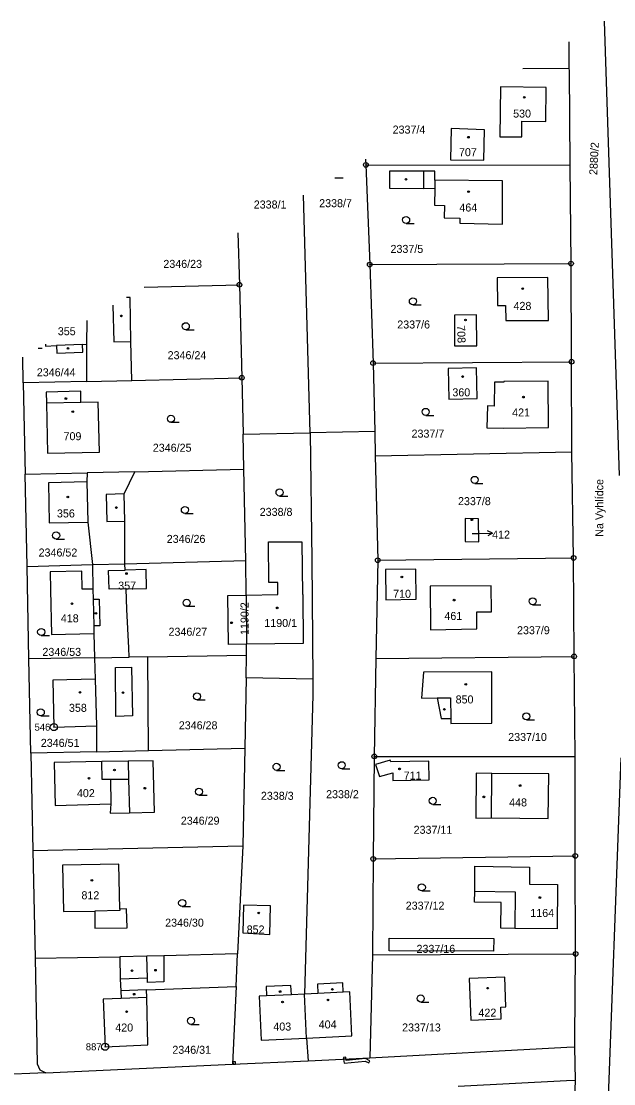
# Model space of a CAD drawing. Extents: x -758836 to -757729, y -1175316 to -1174366.
# Drawn here: x -758715.8 to -758589.9, y -1174936.9 to -1174711.3 of the extents above; entities that cross this region are included whole.
import ezdxf

# ---------------------------------------------------------------- set-up
doc = ezdxf.new("R2010")
doc.units = 0
for name, color, linetype in [('Hranice parcel', 7, 'Continuous'), ('Parcelní čísla', 7, 'Continuous'), ('Pop  PČ popisy', 7, 'Continuous'), ('Vnitřní kresba', 7, 'Continuous'), ('Věcná břemena k části', 7, 'Continuous'), ('Značky bodu BP', 7, 'Continuous'), ('Značky budov', 7, 'Continuous'), ('Značky kultur', 7, 'Continuous')]:
    doc.layers.add(name, color=color, linetype=linetype)

msp = doc.modelspace()

# ---------------------------------------------------------------- linework, layer by layer
at = {"layer": 'Hranice parcel'}
for p, q in [((-758588.72, -1174807.72), (-758591.88, -1174711.27)), ((-758599.38, -1174721.23), (-758599.41, -1174715.61)), ((-758609.26, -1174721.3), (-758599.38, -1174721.23)), ((-758642.64, -1174740.57), (-758642.59, -1174741.77)), ((-758642.59, -1174741.77), (-758641.77, -1174762.95)), ((-758599.02, -1174762.71), (-758599.18, -1174741.82)), ((-758654.45, -1174798.66), (-758655.86, -1174748.2)), ((-758669.76, -1174756.22), (-758669.46, -1174767.22)), ((-758641.77, -1174762.95), (-758599.02, -1174762.71)), ((-758641.77, -1174762.95), (-758641.07, -1174783.86)), ((-758598.91, -1174783.57), (-758599.02, -1174762.71)), ((-758689.66, -1174767.71), (-758669.46, -1174767.22)), ((-758669.46, -1174767.22), (-758668.95, -1174786.98)), ((-758715.38, -1174788.07), (-758715.49, -1174782.63)), ((-758641.07, -1174783.86), (-758640.69, -1174798.38)), ((-758598.81, -1174802.72), (-758598.91, -1174783.57)), ((-758692.34, -1174787.53), (-758668.95, -1174786.98)), ((-758668.95, -1174786.98), (-758668.68, -1174798.94)), ((-758701.96, -1174787.75), (-758715.38, -1174788.07)), ((-758715.38, -1174788.07), (-758714.98, -1174807.46)), ((-758701.96, -1174787.75), (-758692.34, -1174787.53)), ((-758668.68, -1174798.94), (-758654.45, -1174798.66)), ((-758640.69, -1174798.38), (-758654.45, -1174798.66)), ((-758640.69, -1174798.38), (-758640.6, -1174803.53)), ((-758668.51, -1174806.38), (-758668.68, -1174798.94)), ((-758640.6, -1174803.53), (-758598.81, -1174802.72)), ((-758598.48, -1174825.23), (-758598.81, -1174802.72)), ((-758640.6, -1174803.53), (-758640.07, -1174825.71)), ((-758714.98, -1174807.46), (-758701.78, -1174807.15)), ((-758714.57, -1174827.05), (-758714.98, -1174807.46)), ((-758691.67, -1174806.92), (-758701.78, -1174807.15)), ((-758691.67, -1174806.92), (-758668.51, -1174806.38)), ((-758668.07, -1174825.76), (-758668.51, -1174806.38)), ((-758693.78, -1174826.47), (-758668.07, -1174825.76)), ((-758668.02, -1174833.15), (-758668.07, -1174825.76)), ((-758640.07, -1174825.71), (-758640.49, -1174846.58)), ((-758640.07, -1174825.71), (-758598.48, -1174825.23)), ((-758598.36, -1174846.16), (-758598.48, -1174825.23)), ((-758714.57, -1174827.05), (-758700.68, -1174826.66)), ((-758714.17, -1174846.68), (-758714.57, -1174827.05)), ((-758700.68, -1174826.66), (-758693.78, -1174826.47)), ((-758700.68, -1174826.66), (-758700.57, -1174831.84)), ((-758668.02, -1174833.15), (-758667.95, -1174843.55)), ((-758700.36, -1174841.27), (-758700.21, -1174846.44)), ((-758667.93, -1174845.88), (-758667.95, -1174843.55)), ((-758688.92, -1174846.24), (-758667.93, -1174845.88)), ((-758668.03, -1174850.66), (-758667.93, -1174845.88)), ((-758700.21, -1174846.44), (-758714.17, -1174846.68)), ((-758713.75, -1174866.68), (-758714.17, -1174846.68)), ((-758700.21, -1174846.44), (-758692.87, -1174846.31)), ((-758688.92, -1174846.24), (-758692.87, -1174846.31)), ((-758688.8, -1174866.12), (-758688.92, -1174846.24)), ((-758640.49, -1174846.58), (-758640.8, -1174867.37)), ((-758640.49, -1174846.58), (-758598.36, -1174846.16)), ((-758598.14, -1174867.4), (-758598.36, -1174846.16)), ((-758668.03, -1174850.66), (-758668.33, -1174865.66)), ((-758653.88, -1174850.95), (-758668.03, -1174850.66)), ((-758699.8, -1174866.37), (-758713.75, -1174866.68)), ((-758699.8, -1174866.37), (-758688.8, -1174866.12)), ((-758688.8, -1174866.12), (-758668.33, -1174865.66)), ((-758668.33, -1174865.66), (-758668.75, -1174886.35)), ((-758713.75, -1174866.68), (-758713.31, -1174887.37)), ((-758640.8, -1174867.37), (-758641.04, -1174889.13)), ((-758640.8, -1174867.37), (-758598.14, -1174867.4)), ((-758598.11, -1174888.49), (-758598.14, -1174867.4)), ((-758713.31, -1174887.37), (-758668.75, -1174886.35)), ((-758668.75, -1174886.35), (-758669.83, -1174909.28)), ((-758713.31, -1174887.37), (-758712.85, -1174910.23)), ((-758641.04, -1174889.13), (-758598.11, -1174888.49)), ((-758598.03, -1174909.33), (-758598.11, -1174888.49)), ((-758641.04, -1174889.13), (-758641.21, -1174909.49)), ((-758712.85, -1174910.23), (-758694.87, -1174909.97)), ((-758670.16, -1174916.27), (-758669.83, -1174909.28)), ((-758641.21, -1174909.49), (-758641.76, -1174931.39)), ((-758670.16, -1174916.27), (-758670.93, -1174932.75)), ((-758655.2, -1174927.18), (-758655.65, -1174917.85)), ((-758655.2, -1174927.18), (-758654.82, -1174932)), ((-758598.09, -1174936.17), (-758598.23, -1174929.06)), ((-758654.82, -1174932), (-758641.76, -1174931.39)), ((-758710.56, -1174934.59), (-758670.93, -1174932.75)), ((-758670.93, -1174932.75), (-758654.82, -1174932)), ((-758710.56, -1174934.59), (-758721.71, -1174934.99))]:
    msp.add_line(p, q, dxfattribs=at)
for points in [[(-758599.18, -1174741.82), (-758599.37, -1174721.78), (-758599.38, -1174721.23)], [(-758604.27, -1174725.3), (-758614.03, -1174725.19), (-758614.14, -1174735.79), (-758609.49, -1174735.83), (-758609.46, -1174732.48), (-758604.36, -1174732.53), (-758604.27, -1174725.3)], [(-758624.49, -1174734.02), (-758624.61, -1174740.67), (-758617.52, -1174740.79), (-758617.41, -1174734.3), (-758624.49, -1174734.02)], [(-758642.59, -1174741.77), (-758642.29, -1174741.76), (-758599.18, -1174741.82)], [(-758613.6, -1174754.32), (-758613.6, -1174745.16), (-758627.93, -1174745.02), (-758627.91, -1174743.11), (-758630.32, -1174743.1), (-758637.54, -1174743.1), (-758637.59, -1174746.68), (-758630.32, -1174746.76), (-758627.95, -1174746.7), (-758627.98, -1174750.32), (-758625.91, -1174750.36), (-758625.95, -1174753.02), (-758622.61, -1174753.09), (-758622.63, -1174754.16), (-758613.6, -1174754.32)], [(-758612.89, -1174774.8), (-758603.8, -1174774.79), (-758603.93, -1174765.66), (-758614.69, -1174765.74), (-758614.65, -1174771.61), (-758612.92, -1174771.6), (-758612.89, -1174774.8)], [(-758692.34, -1174787.53), (-758692.5, -1174779.28), (-758692.68, -1174769.9), (-758693.47, -1174769.92)], [(-758619.04, -1174780.18), (-758619.12, -1174773.64), (-758623.79, -1174773.67), (-758623.74, -1174780.21), (-758619.04, -1174780.18)], [(-758710.62, -1174779.82), (-758710.61, -1174780.23), (-758708.31, -1174780.13), (-758708.23, -1174781.78), (-758702.72, -1174781.53), (-758702.79, -1174779.88), (-758701.92, -1174779.84), (-758701.96, -1174787.75)], [(-758641.07, -1174783.86), (-758640.95, -1174783.86), (-758598.91, -1174783.57)], [(-758618.97, -1174791.39), (-758619.1, -1174784.86), (-758625.08, -1174784.99), (-758624.97, -1174791.52), (-758618.97, -1174791.39)], [(-758615.37, -1174792.99), (-758616.78, -1174792.96), (-758616.87, -1174797.6), (-758613.34, -1174797.67), (-758603.78, -1174797.55), (-758603.87, -1174787.67), (-758613.28, -1174787.76), (-758613.28, -1174787.93), (-758615.27, -1174787.92), (-758615.37, -1174792.99)], [(-758710.45, -1174792.4), (-758710.2, -1174803), (-758699.16, -1174802.74), (-758699.46, -1174792.14), (-758703.11, -1174792.23), (-758703.16, -1174789.85), (-758710.5, -1174790.02), (-758710.45, -1174792.4)], [(-758654.45, -1174798.66), (-758654.07, -1174825.73), (-758653.88, -1174850.95)], [(-758701.78, -1174807.15), (-758701.86, -1174809.05), (-758710.01, -1174809.26), (-758709.85, -1174817.8), (-758701.65, -1174817.61), (-758700.68, -1174826.66)], [(-758693.78, -1174826.47), (-758693.81, -1174817.42), (-758693.95, -1174811.63), (-758691.67, -1174806.92)], [(-758621.53, -1174816.89), (-758621.47, -1174821.77), (-758618.59, -1174821.78), (-758618.65, -1174816.91), (-758621.53, -1174816.89)], [(-758668.02, -1174833.15), (-758661.26, -1174833.02), (-758661.28, -1174830.45), (-758663.17, -1174830.46), (-758663.26, -1174821.84), (-758656.17, -1174821.78), (-758656.07, -1174832.96), (-758655.97, -1174832.96), (-758655.91, -1174843.41), (-758667.95, -1174843.55)], [(-758692.87, -1174846.31), (-758692.96, -1174844.31), (-758693.34, -1174836.15), (-758693.54, -1174831.79), (-758689.17, -1174831.71), (-758689.27, -1174827.71), (-758693.72, -1174827.81), (-758693.78, -1174826.47)], [(-758638.37, -1174834.15), (-758631.89, -1174833.99), (-758631.97, -1174827.62), (-758638.45, -1174827.69), (-758638.37, -1174834.15)], [(-758700.57, -1174831.84), (-758702.86, -1174831.83), (-758702.9, -1174828.05), (-758709.67, -1174828.17), (-758709.58, -1174831.99), (-758709.35, -1174841.49), (-758700.36, -1174841.27)], [(-758700.57, -1174831.84), (-758700.52, -1174834), (-758699.25, -1174833.97), (-758699.12, -1174839.63), (-758700.39, -1174839.66), (-758700.36, -1174841.27)], [(-758618.99, -1174840.3), (-758619, -1174836.67), (-758615.94, -1174836.65), (-758615.98, -1174831.16), (-758628.92, -1174831.24), (-758628.86, -1174840.52), (-758618.99, -1174840.3)], [(-758667.95, -1174843.55), (-758671.78, -1174843.59), (-758671.9, -1174833.22), (-758668.02, -1174833.15)], [(-758700.21, -1174846.44), (-758700.11, -1174851), (-758709.12, -1174851.17), (-758708.87, -1174861.16), (-758699.84, -1174860.91), (-758699.8, -1174866.37)], [(-758615.85, -1174849.44), (-758630.38, -1174849.48), (-758630.81, -1174854.98), (-758627.47, -1174854.97), (-758626.62, -1174859.3), (-758624.58, -1174859.36), (-758624.58, -1174860.37), (-758615.82, -1174860.34), (-758615.85, -1174849.44)], [(-758653.88, -1174850.95), (-758653.85, -1174854.4), (-758655.65, -1174917.85)], [(-758698.68, -1174868.49), (-758708.83, -1174868.65), (-758708.6, -1174877.77), (-758696.79, -1174877.47), (-758696.89, -1174879.43), (-758692.82, -1174879.34), (-758687.51, -1174879.21), (-758687.77, -1174868.31), (-758693.09, -1174868.4), (-758698.68, -1174868.49)], [(-758637.45, -1174868.17), (-758640.52, -1174869.12), (-758639.72, -1174871.61), (-758636.84, -1174870.85), (-758636.86, -1174872.5), (-758629.18, -1174872.36), (-758629.25, -1174868.4), (-758637.3, -1174868.55), (-758637.45, -1174868.17)], [(-758598.15, -1174949.55), (-758591.43, -1174949.22), (-758588.38, -1174867.67)], [(-758603.84, -1174880.55), (-758603.74, -1174871.11), (-758615.81, -1174870.99), (-758619.14, -1174870.95), (-758619.24, -1174880.46), (-758615.91, -1174880.43), (-758603.84, -1174880.55)], [(-758694.89, -1174899.8), (-758695.08, -1174890.25), (-758707.02, -1174890.49), (-758706.83, -1174900.34), (-758700.16, -1174900.21), (-758700.14, -1174903.88), (-758693.33, -1174903.77), (-758693.41, -1174899.77), (-758694.89, -1174899.8)], [(-758601.88, -1174894.58), (-758601.96, -1174904.02), (-758610.96, -1174903.89), (-758613.93, -1174903.85), (-758613.85, -1174898.43), (-758619.5, -1174898.34), (-758619.47, -1174896.01), (-758619.43, -1174890.7), (-758607.81, -1174890.89), (-758607.85, -1174894.51), (-758601.88, -1174894.58)], [(-758668.61, -1174898.95), (-758668.71, -1174904.84), (-758663, -1174905.16), (-758662.83, -1174899.11), (-758668.61, -1174898.95)], [(-758637.64, -1174908.65), (-758637.64, -1174906), (-758615.4, -1174906.07), (-758615.45, -1174908.71), (-758637.64, -1174908.65)], [(-758712.85, -1174910.23), (-758712.4, -1174932.68), (-758711.84, -1174933.91), (-758710.56, -1174934.59)], [(-758694.87, -1174909.97), (-758694.81, -1174914.65), (-758694.66, -1174917.16), (-758694.6, -1174918.77), (-758698.37, -1174918.92), (-758697.98, -1174929.04), (-758688.92, -1174928.65), (-758689.14, -1174918.56), (-758689.2, -1174916.95), (-758670.16, -1174916.27)], [(-758669.83, -1174909.28), (-758685.48, -1174909.71), (-758689.12, -1174909.81), (-758694.87, -1174909.97)], [(-758641.21, -1174909.49), (-758641.01, -1174909.49), (-758598.03, -1174909.33)], [(-758598.23, -1174929.06), (-758598.22, -1174927.29), (-758598.03, -1174909.33)], [(-758655.65, -1174917.85), (-758658.41, -1174917.98), (-758658.5, -1174915.99), (-758663.8, -1174916.24), (-758663.71, -1174918.23), (-758665.26, -1174918.3), (-758664.84, -1174927.61), (-758655.2, -1174927.18)], [(-758655.2, -1174927.18), (-758645.56, -1174926.74), (-758645.98, -1174917.4), (-758647.43, -1174917.46), (-758647.52, -1174915.47), (-758652.9, -1174915.73), (-758652.81, -1174917.72), (-758655.65, -1174917.85)], [(-758613.07, -1174914.27), (-758620.64, -1174914.53), (-758620.33, -1174923.35), (-758613.83, -1174923.08), (-758613.94, -1174920.59), (-758612.88, -1174920.55), (-758613.07, -1174914.27)], [(-758641.76, -1174931.39), (-758599.94, -1174929.15), (-758598.23, -1174929.06)], [(-758598.09, -1174936.17), (-758599.95, -1174936.27), (-758623.02, -1174937.49)], [(-758598.15, -1174949.55), (-758598.1, -1174938.09), (-758598.09, -1174936.17)]]:
    msp.add_lwpolyline(points, dxfattribs=at)
at = {"layer": 'Pop  PČ popisy'}
for p, q in [((-758619.98, -1174820.07), (-758618.73, -1174820.04)), ((-758618.73, -1174820.04), (-758615.73, -1174819.99)), ((-758615.73, -1174819.99), (-758616.74, -1174819.5)), ((-758615.73, -1174819.99), (-758616.72, -1174820.51))]:
    msp.add_line(p, q, dxfattribs=at)
at = {"layer": 'Vnitřní kresba'}
for p, q in [((-758630.32, -1174743.1), (-758630.32, -1174746.76)), ((-758627.93, -1174745.02), (-758627.95, -1174746.7)), ((-758696.32, -1174771.56), (-758696.15, -1174779.36)), ((-758701.89, -1174774.78), (-758701.92, -1174779.84)), ((-758702.79, -1174779.88), (-758708.31, -1174780.13)), ((-758696.15, -1174779.36), (-758692.5, -1174779.28)), ((-758703.11, -1174792.23), (-758710.45, -1174792.4)), ((-758701.86, -1174809.05), (-758701.65, -1174817.61)), ((-758693.95, -1174811.63), (-758697.76, -1174811.75)), ((-758697.76, -1174811.75), (-758697.63, -1174817.51)), ((-758697.63, -1174817.51), (-758693.81, -1174817.42)), ((-758697.23, -1174827.89), (-758693.72, -1174827.81)), ((-758697.15, -1174831.85), (-758697.23, -1174827.89)), ((-758693.54, -1174831.79), (-758697.15, -1174831.85)), ((-758700.52, -1174834), (-758700.39, -1174839.66)), ((-758695.81, -1174848.52), (-758692.36, -1174848.44)), ((-758695.71, -1174858.88), (-758695.81, -1174848.52)), ((-758692.36, -1174848.44), (-758692.15, -1174858.75)), ((-758700.11, -1174851), (-758699.84, -1174860.91)), ((-758627.47, -1174854.97), (-758624.6, -1174854.96)), ((-758624.6, -1174854.96), (-758624.58, -1174859.36)), ((-758692.15, -1174858.75), (-758695.71, -1174858.88)), ((-758698.62, -1174872.31), (-758698.68, -1174868.49)), ((-758693.09, -1174868.4), (-758692.99, -1174872.25)), ((-758696.87, -1174872.29), (-758698.62, -1174872.31)), ((-758692.99, -1174872.25), (-758696.87, -1174872.29)), ((-758696.87, -1174872.29), (-758696.79, -1174877.47)), ((-758692.99, -1174872.25), (-758692.82, -1174879.34)), ((-758615.91, -1174880.43), (-758615.81, -1174870.99)), ((-758619.47, -1174896.01), (-758610.85, -1174896.13)), ((-758610.85, -1174896.13), (-758610.96, -1174903.89)), ((-758694.88, -1174900.1), (-758700.16, -1174900.21)), ((-758694.89, -1174899.8), (-758694.88, -1174900.1)), ((-758688.99, -1174914.48), (-758689.12, -1174909.81)), ((-758685.48, -1174909.71), (-758685.51, -1174915.22)), ((-758688.99, -1174914.48), (-758694.81, -1174914.65)), ((-758688.97, -1174915.39), (-758688.99, -1174914.48)), ((-758685.51, -1174915.22), (-758688.97, -1174915.39)), ((-758689.2, -1174916.95), (-758694.66, -1174917.16)), ((-758658.41, -1174917.98), (-758663.71, -1174918.23)), ((-758647.43, -1174917.46), (-758652.81, -1174917.72)), ((-758689.14, -1174918.56), (-758694.6, -1174918.77))]:
    msp.add_line(p, q, dxfattribs=at)
at = {"layer": 'Věcná břemena k části'}
for points in [[(-758647.33, -1174931.65), (-758646.83, -1174931.63), (-758646.88, -1174931.23), (-758647.38, -1174931.3)], [(-758641.77, -1174932), (-758642.66, -1174931.55), (-758646.78, -1174931.97), (-758646.83, -1174931.63), (-758647.33, -1174931.65), (-758647.2, -1174932.51), (-758642.76, -1174932.07), (-758641.99, -1174932.45)], [(-758670.82, -1174932.25), (-758670.81, -1174932.74), (-758670.31, -1174932.72), (-758670.32, -1174932.23)]]:
    msp.add_lwpolyline(points, close=True, dxfattribs=at)
at = {"layer": 'Značky bodu BP'}
for centre, radius in [((-758642.59, -1174741.77), 0.5), ((-758642.59, -1174741.77), 0.0303), ((-758641.77, -1174762.95), 0.5), ((-758599.02, -1174762.71), 0.5), ((-758641.77, -1174762.95), 0.0303), ((-758599.02, -1174762.71), 0.0303), ((-758669.46, -1174767.22), 0.5), ((-758669.46, -1174767.22), 0.0303), ((-758641.07, -1174783.86), 0.5), ((-758641.07, -1174783.86), 0.0303), ((-758598.91, -1174783.57), 0.5), ((-758598.91, -1174783.57), 0.0303), ((-758668.95, -1174786.98), 0.5), ((-758668.95, -1174786.98), 0.0303), ((-758640.07, -1174825.71), 0.5), ((-758640.07, -1174825.71), 0.0303), ((-758598.48, -1174825.23), 0.5), ((-758598.48, -1174825.23), 0.0303), ((-758598.36, -1174846.16), 0.5), ((-758598.36, -1174846.16), 0.0303), ((-758708.87, -1174861.16), 0.75), ((-758708.87, -1174861.16), 0.03), ((-758640.8, -1174867.37), 0.5), ((-758640.8, -1174867.37), 0.0303), ((-758641.04, -1174889.13), 0.5), ((-758598.11, -1174888.49), 0.5), ((-758598.11, -1174888.49), 0.0303), ((-758641.04, -1174889.13), 0.0303), ((-758598.03, -1174909.33), 0.5), ((-758598.03, -1174909.33), 0.0303), ((-758697.98, -1174929.04), 0.75), ((-758697.98, -1174929.04), 0.03)]:
    msp.add_circle(centre, radius, dxfattribs=at)
at = {"layer": 'Značky budov'}
for centre in [(-758608.95, -1174727.41), (-758620.81, -1174735.89), (-758634.07, -1174744.83), (-758620.79, -1174747.44), (-758609.27, -1174768.04), (-758694.53, -1174773.83), (-758621.43, -1174774.72), (-758705.86, -1174780.74), (-758622.04, -1174786.71), (-758706.31, -1174791.39), (-758609.12, -1174791.08), (-758704.85, -1174794.18), (-758705.9, -1174812.29), (-758695.59, -1174814.53), (-758620.07, -1174817.13), (-758693.44, -1174828.55), (-758634.95, -1174829.27), (-758705.03, -1174834.95), (-758623.84, -1174834.19), (-758699.94, -1174837.01), (-758661.42, -1174835.83), (-758671.12, -1174839), (-758621.37, -1174852.06), (-758703.32, -1174853.77), (-758694.19, -1174853.84), (-758625.91, -1174857.39), (-758696, -1174870.28), (-758635.44, -1174870.02), (-758701.39, -1174872.01), (-758689.54, -1174874.13), (-758609.83, -1174873.57), (-758617.53, -1174875.97), (-758700.79, -1174893.7), (-758605.63, -1174897.34), (-758665.35, -1174900.62), (-758692.26, -1174912.89), (-758687.28, -1174912.77), (-758691.81, -1174917.87), (-758660.81, -1174917.31), (-758649.71, -1174916.85), (-758616.72, -1174916.59), (-758660.29, -1174919.54), (-758650.65, -1174919.09), (-758693.42, -1174921.59)]:
    msp.add_circle(centre, 0.175, dxfattribs=at)
at = {"layer": 'Značky kultur'}
for p, q in [((-758649.19, -1174744.5), (-758647.44, -1174744.5)), ((-758634.05, -1174754.21), (-758632.3, -1174754.21)), ((-758632.6, -1174771.48), (-758630.85, -1174771.48)), ((-758680.85, -1174776.78), (-758679.1, -1174776.78)), ((-758712.18, -1174780.72), (-758711.36, -1174780.72)), ((-758684, -1174796.43), (-758682.25, -1174796.43)), ((-758629.89, -1174794.97), (-758628.14, -1174794.97)), ((-758619.48, -1174809.41), (-758617.73, -1174809.41)), ((-758660.93, -1174812.08), (-758659.18, -1174812.08)), ((-758681.04, -1174815.79), (-758679.29, -1174815.79)), ((-758708.38, -1174821.21), (-758706.63, -1174821.21)), ((-758680.66, -1174835.5), (-758678.91, -1174835.5)), ((-758607.17, -1174835.18), (-758605.42, -1174835.18)), ((-758711.56, -1174841.7), (-758709.81, -1174841.7)), ((-758678.48, -1174855.37), (-758676.73, -1174855.37)), ((-758711.65, -1174858.76), (-758709.9, -1174858.76)), ((-758608.5, -1174859.62), (-758606.75, -1174859.62)), ((-758661.57, -1174870.34), (-758659.82, -1174870.34)), ((-758647.72, -1174870), (-758645.97, -1174870)), ((-758678.05, -1174875.62), (-758676.3, -1174875.62)), ((-758628.39, -1174877.56), (-758626.64, -1174877.56)), ((-758630.71, -1174895.93), (-758628.96, -1174895.93)), ((-758681.61, -1174899.26), (-758679.86, -1174899.26)), ((-758630.94, -1174919.53), (-758629.19, -1174919.53)), ((-758679.74, -1174924.28), (-758677.99, -1174924.28))]:
    msp.add_line(p, q, dxfattribs=at)
for centre in [(-758634.05, -1174753.46), (-758632.6, -1174770.73), (-758680.85, -1174776.03), (-758629.89, -1174794.22), (-758684, -1174795.68), (-758619.48, -1174808.66), (-758660.93, -1174811.33), (-758681.04, -1174815.04), (-758708.38, -1174820.46), (-758680.66, -1174834.75), (-758607.17, -1174834.43), (-758711.56, -1174840.95), (-758678.48, -1174854.62), (-758711.65, -1174858.01), (-758608.5, -1174858.87), (-758647.72, -1174869.25), (-758661.57, -1174869.59), (-758678.05, -1174874.87), (-758628.39, -1174876.81), (-758630.71, -1174895.18), (-758681.61, -1174898.51), (-758630.94, -1174918.78), (-758679.74, -1174923.53)]:
    msp.add_circle(centre, 0.75, dxfattribs=at)

# ---------------------------------------------------------------- texts
at = {"layer": 'Parcelní čísla'}
for s, p in [('530', (-758611.31, -1174731.72)), ('2337/4', (-758636.91, -1174735.12)), ('707', (-758622.82, -1174739.92)), ('2338/7', (-758652.51, -1174750.75)), ('2338/1', (-758666.41, -1174751.03)), ('464', (-758622.73, -1174751.67)), ('2337/5', (-758637.36, -1174760.46)), ('2346/23', (-758685.61, -1174763.64)), ('428', (-758611.23, -1174772.56)), ('2337/6', (-758635.92, -1174776.51)), ('355', (-758708.03, -1174777.94)), ('2346/24', (-758684.7, -1174783.03)), ('2346/44', (-758712.49, -1174786.66)), ('360', (-758624.22, -1174790.91)), ('421', (-758611.52, -1174795.19)), ('709', (-758706.81, -1174800.23)), ('2337/7', (-758632.89, -1174799.68)), ('2346/25', (-758687.85, -1174802.68)), ('2337/8', (-758623.02, -1174814.02)), ('356', (-758708.21, -1174816.63)), ('2338/8', (-758665.14, -1174816.3)), ('2346/26', (-758684.89, -1174822.04)), ('412', (-758615.77, -1174821.12)), ('2346/52', (-758712.11, -1174824.93)), ('357', (-758695.2, -1174831.96)), ('710', (-758636.8, -1174833.69)), ('461', (-758625.91, -1174838.4)), ('418', (-758707.39, -1174838.9)), ('1190/1', (-758664.16, -1174839.9)), ('2346/27', (-758684.51, -1174841.75)), ('2337/9', (-758610.48, -1174841.43)), ('2346/53', (-758711.3, -1174846.03)), ('850', (-758623.53, -1174856.13)), ('358', (-758705.66, -1174857.91)), ('2346/28', (-758682.33, -1174861.62)), ('2346/51', (-758711.64, -1174865.35)), ('2337/10', (-758612.36, -1174864.1)), ('711', (-758634.56, -1174872.29)), ('402', (-758703.97, -1174876.03)), ('2338/3', (-758664.89, -1174876.59)), ('2338/2', (-758651.04, -1174876.25)), ('448', (-758612.16, -1174878)), ('2346/29', (-758681.9, -1174881.87)), ('2337/11', (-758632.45, -1174883.81)), ('812', (-758703.01, -1174897.71)), ('2337/12', (-758634.13, -1174899.91)), ('1164', (-758607.66, -1174901.47)), ('2346/30', (-758685.23, -1174903.53)), ('852', (-758667.91, -1174904.98)), ('2337/16', (-758631.83, -1174909.09)), ('422', (-758618.68, -1174922.64)), ('420', (-758695.82, -1174925.8)), ('403', (-758662.25, -1174925.59)), ('404', (-758652.61, -1174925.14)), ('2337/13', (-758634.9, -1174925.78)), ('2346/31', (-758683.7, -1174930.53))]:
    msp.add_text(s, height=1.7, dxfattribs=at).set_placement(p)
for s, rotation, p in [('2880/2', 87, (-758593.46, -1174743.94)), ('708', 272, (-758623.23, -1174775.84)), ('1190/2', 90, (-758667.51, -1174841.59))]:
    msp.add_text(s, height=1.7, rotation=rotation, dxfattribs=at).set_placement(p)
at = {"layer": 'Pop  PČ popisy'}
msp.add_text('Na Vyhlídce', height=1.7, rotation=90, dxfattribs=at).set_placement((-758592.16, -1174820.73))
at = {"layer": 'Značky bodu BP'}
for s, p in [('546', (-758712.97, -1174861.91)), ('887', (-758702.08, -1174929.79))]:
    msp.add_text(s, height=1.5, dxfattribs=at).set_placement(p)

doc.saveas('drawing.dxf')
